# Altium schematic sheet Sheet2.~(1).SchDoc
size A; SheetNumber: 2; SheetTotal: 2
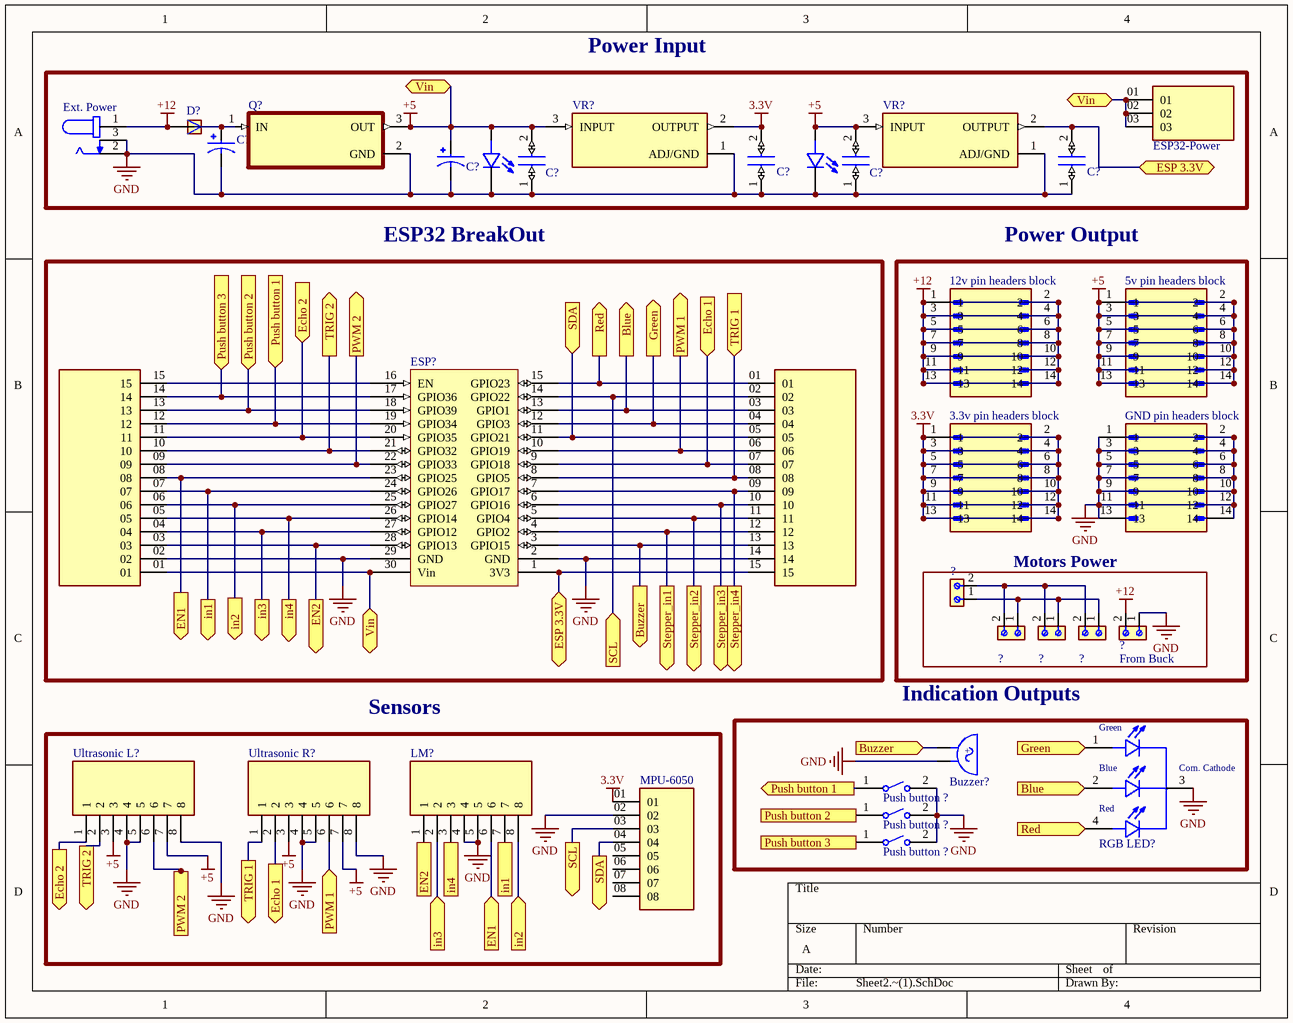
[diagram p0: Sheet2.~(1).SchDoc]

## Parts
(Parts that share a designator on the sheet are numbered #1, #2 ... from top to bottom, then left to right.)
3.3v_pin_headers_block  3.3v pin headers block  [AMPHENOL_52601-S14-4LF]  (value not drawn)
5v_pin_headers_block  5v pin headers block  [AMPHENOL_52601-S14-4LF]  (value not drawn)
12v_pin_headers_block  12v pin headers block  [AMPHENOL_52601-S14-4LF]  (value not drawn)
?#1  LED 5mm  [LED 5mm]  (value not drawn)
?#2  LED 5mm  [LED 5mm]  (value not drawn)
?#3  From Buck  [691213510002]  (value not drawn)
?#4  From Buck  [691213510002]  (value not drawn)
?#5  From Buck  [691213510002]  (value not drawn)
?#6  From Buck  [691213510002]  (value not drawn)
?#7  From Buck  [691213510002]
Buzzer?  Buzzer  [Buzzer 5V]  (value not drawn)
C?#1  CAP  33UF 50V RADIAL  [CAP  33UF 50V RADIAL]  (value not drawn)
C?#2  CAP  33UF 50V RADIAL  [CAP  33UF 50V RADIAL]  (value not drawn)
C?#3  Ceramic Capacitor 100nF  [C320C]  (value not drawn)
C?#4  Ceramic Capacitor 100nF  [C320C]  (value not drawn)
C?#5  Ceramic Capacitor 100nF  [C320C]  (value not drawn)
C?#6  Ceramic Capacitor 100nF  [C320C]  (value not drawn)
D?  RL207  [DIOAD1300W80L670D310]  (value not drawn)
ESP32-Power  TS-103-T-A-1  [SAMTEC_TS-103-T-A-1]  (value not drawn)
ESP?  ESP32DEVKITV1  [ESP32DEVKITV1]  (value not drawn)
Ext._Power  DC Power Jack Female Socket  [DC Power Jack Female Socket]  (value not drawn)
GND_pin_headers_block  GND pin headers block  [AMPHENOL_52601-S14-4LF]  (value not drawn)
J?#1  TS-115-T-A-1  [SAMTEC_TS-115-T-A-1]  (value not drawn)
J?#2  TS-115-T-A-1  [SAMTEC_TS-115-T-A-1]  (value not drawn)
LM?  Pin header female block 8 pin  [Pin header female block 8 pin]  (value not drawn)
MPU-6050  MPU-6050  [MPU-6050]  (value not drawn)
Push_button_?#1  FSM8JRT  [TE_FSM8JRT]  (value not drawn)
Push_button_?#2  FSM8JRT  [TE_FSM8JRT]  (value not drawn)
Push_button_?#3  FSM8JRT  [TE_FSM8JRT]  (value not drawn)
Q?  LM7805CT  [TO254P1054X470X1955-3]  (value not drawn)
RGB_LED?  common cathode  [LED RGB 5mm]  (value not drawn)
Ultrasonic_L?  Pin header female block 8 pin  [Pin header female block 8 pin]  (value not drawn)
Ultrasonic_R?  Pin header female block 8 pin  [Pin header female block 8 pin]  (value not drawn)
VR?#1  LM1117T-3.3  [TO254P1054X470X1955-3]  (value not drawn)
VR?#2  LM1117T-3.3  [TO254P1054X470X1955-3]  (value not drawn)

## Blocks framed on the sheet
Power Input: ?#1 ?#2 C?#1-C?#6 D? ESP32-Power Ext._Power Q? VR?#1 VR?#2
ESP32 BreakOut: ESP? J?#1 J?#2
Power Output: 3.3v_pin_headers_block 5v_pin_headers_block 12v_pin_headers_block GND_pin_headers_block
Motors Power: ?#3-?#7
Indication Outputs: Buzzer? Push_button_?#1-Push_button_?#3 RGB_LED?
Sensors: LM? MPU-6050 Ultrasonic_L? Ultrasonic_R?

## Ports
Blue (in, see Sheet1[2B], Sheet1[4B], Sheet2[2B]), Blue (out, see Sheet1[2B], Sheet1[4B], Sheet2[4D]), Buzzer (in, see Sheet1[2C], Sheet1[4A], Sheet2[2C]), Buzzer (out, see Sheet1[2C], Sheet1[4A], Sheet2[3C]), Echo 1 (in, see Sheet1[3B], Sheet1[4B], Sheet2[1D]), Echo 1 (out, see Sheet1[3B], Sheet1[4B], Sheet2[3B]), Echo 2 (in, see Sheet1[1B], Sheet1[3B], Sheet2[1D]), Echo 2 (out, see Sheet1[1B], Sheet1[3B], Sheet2[1B]), EN1 (in, see Sheet1[1C], Sheet1[4C], Sheet2[1C]), EN1 (out, see Sheet1[1C], Sheet1[4C], Sheet2[2D]), EN2 (in, see Sheet1[2C], Sheet1[4C], Sheet2[1C]), EN2 (out, see Sheet1[2C], Sheet1[4C], Sheet2[2D]), ESP 3.3V (bidir, see Sheet1[2C], Sheet1[3A], Sheet2[2C]), ESP 3.3V (bidir, see Sheet1[2C], Sheet1[3A], Sheet2[4A]), Green (in, see Sheet1[3B], Sheet1[4B], Sheet2[3B]), Green (out, see Sheet1[3B], Sheet1[4B], Sheet2[4C]), in1 (in, see Sheet1[1C], Sheet1[4C], Sheet2[1C]), in1 (out, see Sheet1[1C], Sheet1[4C], Sheet2[2D]), in2 (in, see Sheet1[1C], Sheet1[4C], Sheet2[1C]), in2 (out, see Sheet1[1C], Sheet1[4C], Sheet2[2D]), in3 (in, see Sheet1[1C], Sheet1[4C], Sheet2[1C]), in3 (out, see Sheet1[1C], Sheet1[4C], Sheet2[2D]), in4 (in, see Sheet1[1C], Sheet1[4C], Sheet2[1C]), in4 (out, see Sheet1[1C], Sheet1[4C], Sheet2[2D]), Push button 1 (in, see Sheet1[1B], Sheet1[4C], Sheet2[3D]), Push button 1 (out, see Sheet1[1B], Sheet1[4C], Sheet2[1B]), Push button 2 (in, see Sheet1[1B], Sheet1[4D], Sheet2[3D]), Push button 2 (out, see Sheet1[1B], Sheet1[4D], Sheet2[1B]), Push button 3 (in, see Sheet1[1B], Sheet1[4D], Sheet2[3D]), Push button 3 (out, see Sheet1[1B], Sheet1[4D], Sheet2[1B]), PWM 1 (in, see Sheet1[3B], Sheet1[4B], Sheet2[3B]), PWM 1 (out, see Sheet1[3B], Sheet1[4B], Sheet2[2D]), PWM 2 (in, see Sheet1[2B], Sheet1[4B], Sheet2[2B]), PWM 2 (out, see Sheet1[2B], Sheet1[4B], Sheet2[1D]), Red (in, see Sheet1[2B], Sheet1[4B], Sheet2[2B]), Red (out, see Sheet1[2B], Sheet1[4B], Sheet2[4D]), SCL (in, see Sheet1[2C], Sheet1[3C], Sheet2[2D]), SCL (out, see Sheet1[2C], Sheet1[3C], Sheet2[2C]), SDA (in, see Sheet1[2B], Sheet1[4C], Sheet2[2D]), SDA (out, see Sheet1[2B], Sheet1[4C], Sheet2[2B]), Stepper_in1 (out, see Sheet1[2C]), Stepper_in2 (out, see Sheet1[3C]), Stepper_in3 (out, see Sheet1[3C]), Stepper_in4 (out, see Sheet1[3C]), TRIG 1 (in, see Sheet1[3B], Sheet1[4B], Sheet2[1D]), TRIG 1 (out, see Sheet1[3B], Sheet1[4B], Sheet2[3B]), TRIG 2 (out, see Sheet1[1B], Sheet1[3B], Sheet2[1D]), TRIG 2 (out, see Sheet1[1B], Sheet1[3B], Sheet2[2B]), Vin (bidir, see Sheet1[2A], Sheet1[2C], Sheet2[2A], Sheet2[2C]), Vin (bidir, see Sheet1[2A], Sheet1[2C], Sheet2[2A], Sheet2[4A]), Vin (bidir, see Sheet1[2A], Sheet1[2C], Sheet2[2C], Sheet2[4A])

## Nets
3.3V: 3.3v_pin_headers_block.1 3.3v_pin_headers_block.2 3.3v_pin_headers_block.3 3.3v_pin_headers_block.4 3.3v_pin_headers_block.5 3.3v_pin_headers_block.6 3.3v_pin_headers_block.7 3.3v_pin_headers_block.8 3.3v_pin_headers_block.9 3.3v_pin_headers_block.10 3.3v_pin_headers_block.11 3.3v_pin_headers_block.12 3.3v_pin_headers_block.13 3.3v_pin_headers_block.14 C?#4.2 MPU-6050.01 VR?#1.2(OUTPUT)
+5: 5v_pin_headers_block.1 5v_pin_headers_block.2 5v_pin_headers_block.3 5v_pin_headers_block.4 5v_pin_headers_block.5 5v_pin_headers_block.6 5v_pin_headers_block.7 5v_pin_headers_block.8 5v_pin_headers_block.9 5v_pin_headers_block.10 5v_pin_headers_block.11 5v_pin_headers_block.12 5v_pin_headers_block.13 5v_pin_headers_block.14 ?#1.A ?#2.A C?#2.P C?#3.2 C?#5.2 ESP32-Power.01 ESP32-Power.02 ESP32-Power.03 ESP?.30(Vin) J?#1.01 Q?.3(OUT) Ultrasonic_L?.3 Ultrasonic_L?.7 Ultrasonic_R?.3 Ultrasonic_R?.7 VR?#1.3(INPUT) VR?#2.3(INPUT) ; port Vin
+12: 12v_pin_headers_block.1 12v_pin_headers_block.2 12v_pin_headers_block.3 12v_pin_headers_block.4 12v_pin_headers_block.5 12v_pin_headers_block.6 12v_pin_headers_block.7 12v_pin_headers_block.8 12v_pin_headers_block.9 12v_pin_headers_block.10 12v_pin_headers_block.11 12v_pin_headers_block.12 12v_pin_headers_block.13 12v_pin_headers_block.14 ?#7.2 D?.A Ext._Power.1
GND: ?#1.C ?#2.C ?#7.1 Buzzer?.NEG C?#1.N C?#2.N C?#3.1 C?#4.1 C?#5.1 C?#6.1 ESP?.2(GND) ESP?.29(GND) Ext._Power.2 Ext._Power.3 GND_pin_headers_block.1 GND_pin_headers_block.2 GND_pin_headers_block.3 GND_pin_headers_block.4 GND_pin_headers_block.5 GND_pin_headers_block.6 GND_pin_headers_block.7 GND_pin_headers_block.8 GND_pin_headers_block.9 GND_pin_headers_block.10 GND_pin_headers_block.11 GND_pin_headers_block.12 GND_pin_headers_block.13 GND_pin_headers_block.14 J?#1.02 J?#2.14 LM?.4 LM?.5 MPU-6050.02 Push_button_?#1.2 Push_button_?#2.2 Push_button_?#3.2 Q?.2(GND) RGB_LED?.3(Com._Cathode) Ultrasonic_L?.4 Ultrasonic_L?.5 Ultrasonic_L?.8 Ultrasonic_R?.4 Ultrasonic_R?.5 Ultrasonic_R?.8 VR?#1.1(ADJ/GND) VR?#2.1(ADJ/GND)
Blue: ESP?.13(GPIO1) J?#2.03 RGB_LED?.2(BLUE) ; port Blue
Buzzer: Buzzer?.POS ESP?.3(GPIO15) J?#2.13 ; port Buzzer
Echo 1: ESP?.9(GPIO18) J?#2.07 Ultrasonic_R?.2 ; port Echo 1
Echo 2: ESP?.20(GPIO35) J?#1.11 Ultrasonic_L?.1 ; port Echo 2
EN1: ESP?.23(GPIO25) J?#1.08 LM?.6 ; port EN1
EN2: ESP?.28(GPIO13) J?#1.03 LM?.1 ; port EN2
ESP 3.3V: C?#6.2 ESP?.1(3V3) J?#2.15 VR?#2.2(OUTPUT) ; port ESP 3.3V
Green: ESP?.12(GPIO3) J?#2.04 RGB_LED?.1(Green) ; port Green
in1: ESP?.24(GPIO26) J?#1.07 LM?.7 ; port in1
in2: ESP?.25(GPIO27) J?#1.06 LM?.8 ; port in2
in3: ESP?.27(GPIO12) J?#1.04 LM?.2 ; port in3
in4: ESP?.26(GPIO14) J?#1.05 LM?.3 ; port in4
Push button 1: ESP?.19(GPIO34) J?#1.12 Push_button_?#1.1 ; port Push button 1
Push button 2: ESP?.18(GPIO39) J?#1.13 Push_button_?#2.1 ; port Push button 2
Push button 3: ESP?.17(GPIO36) J?#1.14 Push_button_?#3.1 ; port Push button 3
PWM 1: ESP?.10(GPIO19) J?#2.06 Ultrasonic_R?.6 ; port PWM 1
PWM 2: ESP?.22(GPIO33) J?#1.09 Ultrasonic_L?.6 ; port PWM 2
Red: ESP?.15(GPIO23) J?#2.01 RGB_LED?.4(Red) ; port Red
SCL: ESP?.14(GPIO22) J?#2.02 MPU-6050.03 ; port SCL
SDA: ESP?.11(GPIO21) J?#2.05 MPU-6050.04 ; port SDA
Stepper_in1: ESP?.4(GPIO2) J?#2.12 ; port Stepper_in1
Stepper_in2: ESP?.5(GPIO4) J?#2.11 ; port Stepper_in2
Stepper_in3: ESP?.6(GPIO16) J?#2.10 ; port Stepper_in3
Stepper_in4: ESP?.7(GPIO17) J?#2.09 ; port Stepper_in4
TRIG 1: ESP?.8(GPIO5) J?#2.08 Ultrasonic_R?.1 ; port TRIG 1
TRIG 2: ESP?.21(GPIO32) J?#1.10 Ultrasonic_L?.2 ; port TRIG 2
Net?#3_1: ?#3.1 ?#4.1 ?#5.1 ?#6.1
Net?#3_2: ?#3.2 ?#4.2 ?#5.2 ?#6.2
NetC?#1_P: C?#1.P D?.C Q?.1(IN)
NetESP?_16: ESP?.16(EN) J?#1.15

Not connected (* = marked no-connect by the designer): MPU-6050 05 06 07 08

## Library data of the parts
3.3v_pin_headers_block 5v_pin_headers_block 12v_pin_headers_block GND_pin_headers_block = 52601-S14-4LF: MF: {'manufacturer': u'Amphenol ICC (FCI)'}
?#1 ?#2 = LED 5mm: Red 623nm LED Indication - Discrete 1.9V Radial; MF: {'manufacturer': u'Wurth Elektronik'}; MP: 151054RS03000
?#3-?#7 = Terminal Block: 2 Position Wire to Board Terminal Block Horizontal with Board 0.200 (5.08mm) Through Hole; MF: Wurth Electronics
Buzzer? = Buzzer 5V: BUZZER 2.3KHZ 4-6VDC; MF: {'manufacturer': u'Soberton Inc.'}; MP: WST-1205S
C?#1 C?#2 = CAP  33UF 50V RADIAL: NHG-A; MF: {'manufacturer': u'Panasonic'}; MP: ECA1HHG330I
C?#3-C?#6 = Ceramic Capacitor 100nF: 0.1ÂµF Â±20% 50V Ceramic Capacitor Z5U Radial; MF: KEMET; MP: C320C104M5U5TA
D? = RL207: Semiconductors and Actives, Power Diodes, Discretes (diodes, transistors, thyristors ...), Diodes; MF: {'manufacturer': u'Diodes Inc.'}
ESP32-Power = TS-103-T-A-1: MF: {'manufacturer': u'Samtec'}
Ext._Power = DC Power Jack Female Socket: 2.0 mm Center Pin, 2.5 A, Right Angle, Through Hole, Dc Power Jack Connector; MF: {'manufacturer': u'CUI Devices'}; MP: PJ-002A
J?#1 J?#2 = TS-115-T-A-1: MF: {'manufacturer': u'Samtec'}
LM? Ultrasonic_L? Ultrasonic_R? = Pin header female block 8 pin: MF: {'manufacturer': u'TE Connectivity'}; MP: 5-534998-4
Push_button_?#1-Push_button_?#3 = FSM8JRT: Tactile Switches PUSHBUTTON SWITCH TACT; MF: {'manufacturer': u'TE Connectivity'}
Q? = LM7805CT/NOPB: MF: {'manufacturer': u'Texas Instruments'}
RGB_LED? = LED RGB 5mm: MF: {'manufacturer': u'Kingbright'}; MP: WP154A4SUREQBFZGC
VR?#1 VR?#2 = LM1117T-3.3/NOPB: MF: {'manufacturer': u'Texas Instruments'}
